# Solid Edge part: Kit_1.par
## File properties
Dokumentum tartalom típus: 0
Last saved by: ahadarics
Revision: 76
Sűrűség: 0,000 kg/m^3
Pontosság: 0,990
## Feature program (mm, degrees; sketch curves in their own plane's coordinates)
base feature "unnamed BaseFeature 1"
thread "unnamed Thread 1"
chamfer "unnamed Chamfer 1"
sketch for "Furat_1" plane through (0, -49.25, 13.5) normal (0, 0, 1) x-axis (0, 1, 0)
  hole centre (0.25, 0) bore radius 4.283
hole "Furat_1" nominal diameter 9.728 finite  ThreadDepth = 7.5 mm
chamfer "Letörés_2" setback 0.7
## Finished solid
Body 1: solid body, 49 faces, 55 edges, 9 vertices.
  Faces by surface: cylinder 16, plane 15, cone 11, torus 7
  Edges by curve: circle 46, line 7, intersection 2
Bounding box of the edges (mm; curved faces can reach further): 30.000 x 39.500 x 28.500, from (-15, -79, -15) to (15, -39.5, 13.5).
Cylindrical faces by radius (mm): R4.283 x3, R5.25 x1, R5.55 x1, R7 x3, R7.05 x1, R8.05 x1, R8.1 x1, R9.85 x1, R11 x2, R13.5 x1, R15 x1
Conical faces (half-angle, radius in mm at the cone's reference point): 0.1788 deg R6.7706 x1, 15 deg R8.05 x1, 17.2279 deg R5.55 x1, 19.7315 deg R5.0176 x1, 21.0856 deg R5.55 x1, 21.5244 deg R6.2703 x1, 45 deg R4.283 x1, 45 deg R7.15 x1, 45 deg R7.2 x1, 45 deg R11 x1, 60 deg R10.425 x1
Toroidal faces (ring radius, tube radius in mm): R5.2 r0.2 x1, R5.3 r0.3 x1, R6.6424 r0.4 x1, R6.85 r0.2 x1, R7.85 r0.2 x1, R7.9 r0.2 x2
Planar faces by outward normal: +y 5, +z 2, -y 8
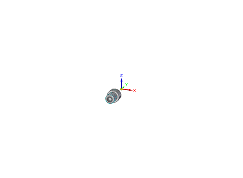
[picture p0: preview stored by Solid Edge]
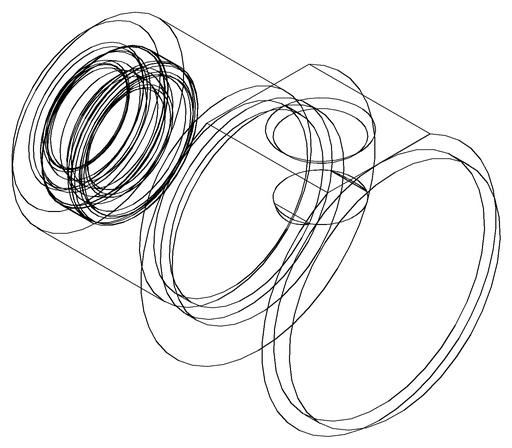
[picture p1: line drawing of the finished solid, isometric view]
